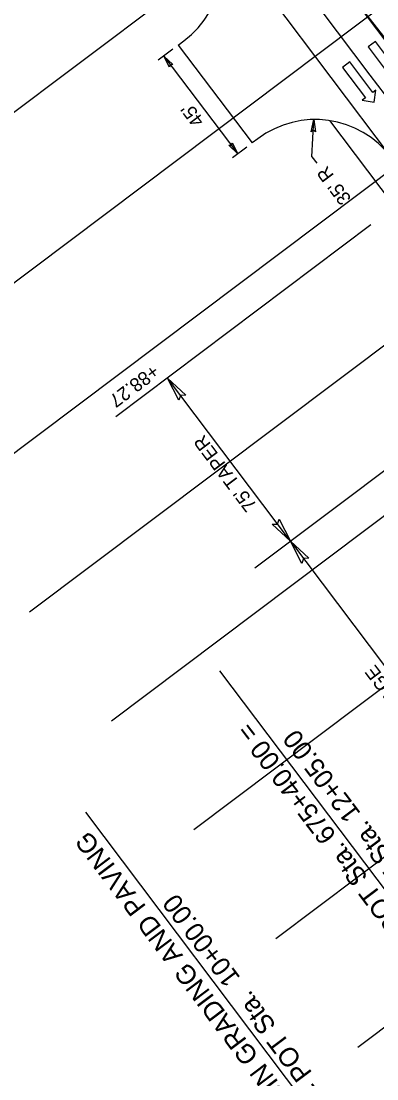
# Model space of a CAD drawing. Extents: x 1262309 to 1264352, y 775189 to 777755.
# Drawn here: x 1262992.3 to 1263122.7, y 776491.3 to 776879.5 of the extents above; entities that cross this region are included whole.
import ezdxf

# ---------------------------------------------------------------- set-up
doc = ezdxf.new("R2010")
doc.units = 0
for name, color, linetype in [('Prop Dimension', 7, 'Continuous'), ('Prop Dimension Text', 7, 'Continuous'), ('Prop EOT', 7, 'Continuous'), ('Prop Horizontal Alignment Direction Label', 7, 'Continuous'), ('Prop Horizontal Alignment Station Label', 7, 'Continuous'), ('Prop Lane Arrow CELL', 7, 'Continuous'), ('Prop Lane Lines', 7, 'Continuous'), ('Prop Paved Shoulder', 7, 'Continuous'), ('Prop Terminator CELL', 7, 'Continuous'), ('Scratch_Level_3', 7, 'Continuous')]:
    doc.layers.add(name, color=color, linetype=linetype)

msp = doc.modelspace()

# ---------------------------------------------------------------- linework, layer by layer
at = {"layer": 'Prop Dimension'}
for p, q in [((1263047.94, 776869.24), (1263042.58, 776865.16)), ((1263044.57, 776866.67), (1263071.81, 776830.86)), ((1263098.92, 776829.75), (1263099.59, 776843.41)), ((1263075.01, 776833.29), (1263069.82, 776829.34)), ((1263098.92, 776829.75), (1263100.74, 776827.35)), ((1263027.07, 776734.48), (1263120.54, 776804.88)), ((1263091.06, 776688.65), (1263045.99, 776748.48)), ((1263077.93, 776678.88), (1263165.67, 776744.97)), ((1263091.05, 776688.64), (1263196.28, 776548.94))]:
    msp.add_line(p, q, dxfattribs=at)
at = {"layer": 'Prop Dimension Text'}
for points in [[(1263050.17, 776740.36), (1263045.99, 776748.48), (1263052.72, 776742.21), (1263050.75, 776742.17)], [(1263086.88, 776696.77), (1263091.06, 776688.65), (1263084.34, 776694.91), (1263086.31, 776694.96)], [(1263095.23, 776680.52), (1263091.05, 776688.64), (1263097.78, 776682.38), (1263095.81, 776682.33)]]:
    msp.add_lwpolyline(points, close=True, dxfattribs=at)
at = {"layer": 'Prop EOT'}
for p, q in [((1263049.93, 776870.75), (1263052, 776872.31)), ((1263049.93, 776870.75), (1263077, 776834.8)), ((1263079.08, 776836.37), (1263077, 776834.8))]:
    msp.add_line(p, q, dxfattribs=at)
for centre, start, end in [((1263030.95, 776900.27), 306.9874, 36.9874), ((1263100.13, 776808.41), 36.9874, 126.9874)]:
    msp.add_arc(centre, 35, start, end, dxfattribs=at)
at = {"layer": 'Prop Horizontal Alignment Direction Label'}
msp.add_line((1263145.97, 776533.85), (1263065.13, 776641.04), dxfattribs=at)
at = {"layer": 'Prop Horizontal Alignment Station Label'}
msp.add_line((1263102.41, 776474.57), (1263016.02, 776589.26), dxfattribs=at)
at = {"layer": 'Prop Lane Arrow CELL'}
for p, q in [((1263122.17, 776872.03), (1263119.54, 776870.04)), ((1263130.6, 776860.84), (1263122.17, 776872.03)), ((1263119.54, 776870.04), (1263127.96, 776858.86)), ((1263112.76, 776864.53), (1263110.12, 776862.55)), ((1263121.18, 776853.35), (1263112.76, 776864.53)), ((1263110.12, 776862.55), (1263118.54, 776851.36)), ((1263118.54, 776851.36), (1263117.35, 776850.46)), ((1263122.38, 776854.25), (1263121.18, 776853.35)), ((1263121.72, 776849.81), (1263122.38, 776854.25)), ((1263117.35, 776850.46), (1263121.72, 776849.81))]:
    msp.add_line(p, q, dxfattribs=at)
at = {"layer": 'Prop Lane Lines'}
for p, q in [((1263128.09, 776829.47), (1263058.9, 776921.33)), ((1263290.52, 776653.71), (1263113.2, 776889.12)), ((1263113.42, 776888.84), (1263294.89, 776656.99)), ((1263280.15, 776647.53), (1263120.31, 776859.74))]:
    msp.add_line(p, q, dxfattribs=at)
msp.add_lwpolyline([(1263120.31, 776859.74), (1262792.29, 777295.24)], dxfattribs=at)
at = {"layer": 'Prop Paved Shoulder'}
msp.add_line((1263105.37, 776843.02), (1263128.66, 776812.1), dxfattribs=at)
at = {"layer": 'Prop Terminator CELL'}
for points in [[(1263046.68, 776862.62), (1263044.57, 776866.67), (1263047.94, 776863.55), (1263046.96, 776863.53)], [(1263098.6, 776838.95), (1263099.59, 776843.41), (1263100.17, 776838.85), (1263099.4, 776839.46)], [(1263069.71, 776834.91), (1263071.81, 776830.86), (1263068.44, 776833.97), (1263069.42, 776834)]]:
    msp.add_lwpolyline(points, close=True, dxfattribs=at)
at = {"layer": 'Scratch_Level_3'}
for p, q in [((1262905.17, 776782.53), (1263400.27, 777155.45)), ((1262935.25, 776742.59), (1263430.35, 777115.51)), ((1262965.33, 776702.65), (1263460.43, 777075.57)), ((1262995.41, 776662.72), (1263490.52, 777035.63)), ((1263025.5, 776622.78), (1263520.6, 776995.69)), ((1263055.58, 776582.84), (1263550.68, 776955.75)), ((1263085.66, 776542.9), (1263580.76, 776915.82)), ((1263115.74, 776502.96), (1263610.84, 776875.88))]:
    msp.add_line(p, q, dxfattribs=at)

# ---------------------------------------------------------------- texts
at = {"layer": 'Prop Dimension'}
msp.add_text("35' R", height=5, rotation=127.0213, dxfattribs=at).set_placement((1263113.57, 776814.46))
at = {"layer": 'Prop Dimension Text'}
for s, rotation, p in [("45'", 126.9874, (1263059.69, 776842.99)), ('+88.27', 216.9874, (1263040.55, 776753.81)), ("75' TAPER", 126.9874, (1263078.95, 776701.84)), ("175' STORAGE", 126.9874, (1263150.25, 776606.14))]:
    msp.add_text(s, height=5, rotation=rotation, dxfattribs=at).set_placement(p)
at = {"layer": 'Prop Horizontal Alignment Direction Label'}
for s, p in [('-L- POT Sta. 675+40.00 =', (1263141.32, 776536.76)), ('-Y- POT Sta. 12+05.00', (1263150.83, 776543.92))]:
    msp.add_text(s, height=7, rotation=126.9874, dxfattribs=at).set_placement(p)
at = {"layer": 'Prop Horizontal Alignment Station Label'}
for s, p in [('BEGIN GRADING AND PAVING', (1263098.77, 776474.33)), ('-Y- POT Sta.  10+00.00', (1263108.28, 776481.49))]:
    msp.add_text(s, height=7, rotation=126.9874, dxfattribs=at).set_placement(p)

doc.saveas('drawing.dxf')
